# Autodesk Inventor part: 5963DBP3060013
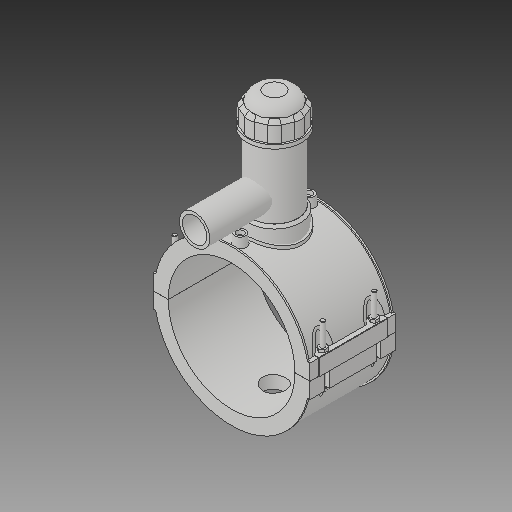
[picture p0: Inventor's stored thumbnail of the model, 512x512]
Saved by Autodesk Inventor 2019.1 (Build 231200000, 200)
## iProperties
Created: 2017-07
Part Number: 5963DBP3060013
Material: Generic
Description: PLASSON TAPPING SADDLE 6''DIPS x 1 1/4''IPS
Document SubType Name: Modeling
Designer: KIM
Density: 1 g/cm^3
Appearance: Default
Author: KIM
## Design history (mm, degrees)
derived "5963DBP_5963BUP.ipt"
feature "Solid1::5963DBP_5963BUP.ipt"
feature "Solid2::5963DBP_5963BUP.ipt"
feature "Solid3::5963DBP_5963BUP.ipt"
tag "TaggingFeature1"
body "Solid1"
body "Solid2"
body "Solid3"
other parameters: "d0" = 174.5, "d2" = 215.9, "d3" = 43.625, "d4" = 118.11, "d5" = 0, "d6" = 0.1, "d8" = 0, "d19" = 6, "d20" = 6, "d21" = 70.866, "d23" = 0, "d24" = 35.433, "d26" = 0, "d27" = 3, "d28" = 3, "d29" = 3, "d30" = 58.16667, "d31" = 6, "d32" = 0, "d33" = 0, "d34" = 0.6, "d40" = 108.888, "d41" = 75.035, "d43" = 0, "d45" = 0, "d47" = 175.566, "d70" = 15, "d72" = 0, "d73" = 6, "d75" = 5, "d76" = 0, "d77" = 8.725, "d78" = 117.25, "d79" = 15, "d80" = 47.244, "d82" = 5 deg, "d84" = 4, "d85" = 14, "d86" = 0, "d87" = 3, "d88" = 0, "d89" = 1, "d90" = 1, "d91" = 94.488, "d92" = 0, "d93" = 0.5, "d94" = 91.84211, "d96" = 213.588, "d97" = 2.3622, "d98" = 0, "d120" = 140 deg, "d121" = 24.228, "d122" = 20 deg, "d123" = 418.8, "d124" = 125.64, "d126" = 0, "d143" = 179.735, "d145" = 26.84615, "d149" = 2.6175, "d150" = 29.53077, "d153" = 118.11, "d154" = 0, "d156" = 104.7, "d157" = 160 deg, "d159" = 6.98, "d161" = 2.6175, "d162" = 70.866, "d163" = 0, "d164" = 87.25, "d167" = 17.45, "d168" = 102.14634, "d170" = 3.4335, "d172" = 0, "d173" = 1, "d175" = 87.25, "d176" = 20 deg, "d177" = 12.215, "d178" = 34.9, "d180" = 0, "d183" = 13.96, "d184" = 9.772, "d185" = 38.38575, "d186" = 38.38575, "d187" = 104.7, "d188" = 10.47, "d189" = 12.215, "d190" = 0, "d191" = 157.05, "d193" = 7.3248, "d194" = 4.13385, "d195" = 90 deg, "d197" = 0, "d199" = 0, "d200" = 17.45, "d202" = 0, "d203" = 177.038, "d204" = 71.28325, "d205" = 52.5245, "d206" = 63.77975, "d207" = 132.7785, "d208" = 138.08964, "d209" = 164.64534, "d210" = 64.5301, "d211" = 75.035, "d212" = 60.028, "d213" = 39.5766, "d216" = 0, "d217" = 17.45, "d218" = 17.45, "d219" = 3.49, "d222" = 174.5, "d224" = 0, "d225" = 65.024, "d226" = 42.1, "d227" = 33.68, "d228" = 109.982, "d230" = 5.235, "d_" = 174.5, "B_" = 215.9, "L_" = 118.11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
